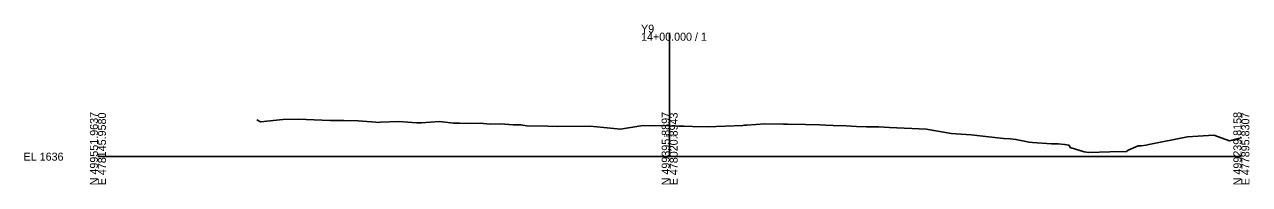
# Model space of a CAD drawing. Extents: x -26 to 403, y -99 to 4540.
# Drawn here: x -25.7 to 402.8, y 3990.3 to 4046.1 of the extents above; entities that cross this region are included whole.
import ezdxf

# ---------------------------------------------------------------- set-up
doc = ezdxf.new("R2010")
doc.units = 0
for name, color, linetype in [('Exist Cross Section Cell', 7, 'Continuous'), ('Exist XS Center Line Elevation Label', 7, 'Continuous'), ('Exist XS Ground Line', 7, 'Continuous')]:
    doc.layers.add(name, color=color, linetype=linetype)

msp = doc.modelspace()

# ---------------------------------------------------------------- linework, layer by layer
at = {"layer": 'Exist Cross Section Cell'}
for p, q in [((200, 4000), (200, 4043.26)), ((0, 4000), (200, 4000)), ((200, 4000), (400, 4000))]:
    msp.add_line(p, q, dxfattribs=at)
at = {"layer": 'Exist XS Ground Line'}
msp.add_lwpolyline([(55.54, 4012.85), (56.91, 4012.2), (64.71, 4013.01), (70.07, 4013.06), (81.2, 4012.6), (85.97, 4012.59), (90.99, 4012.54), (97.24, 4012.02), (98.1, 4011.97), (98.79, 4012), (105.22, 4012.3), (111.6, 4011.76), (112.33, 4011.81), (113.24, 4011.78), (119.45, 4012.26), (124.42, 4011.74), (126.56, 4011.71), (129.23, 4011.53), (133.68, 4011.68), (137.24, 4011.39), (140.79, 4011.5), (145.23, 4011.08), (147.91, 4011.06), (150.06, 4010.78), (157.38, 4010.69), (160.87, 4010.51), (172.13, 4010.63), (176.95, 4010.2), (182.79, 4009.58), (189.86, 4010.75), (190.87, 4010.93), (200, 4010.73), (203.22, 4010.66), (204.96, 4010.63), (207.94, 4010.52), (213.25, 4010.37), (225.54, 4010.89), (226.18, 4010.95), (226.96, 4011), (233.29, 4011.42), (239.77, 4011.31), (240.41, 4011.31), (241.2, 4011.32), (247.52, 4011.28), (252.59, 4011.08), (254.64, 4010.98), (257.19, 4010.88), (261.75, 4010.8), (265.41, 4010.57), (268.87, 4010.43), (273.19, 4010.41), (276.9, 4010.23), (289.8, 4009.6), (290.38, 4009.52), (291.09, 4009.42), (298.52, 4008.04), (305.47, 4007.58), (316.81, 4006.33), (319.15, 4006.17), (321.14, 4006.01), (325.8, 4005.01), (326.98, 4004.92), (333.57, 4004.53), (334.49, 4004.51), (335.88, 4004.48), (338.15, 4004.3), (339.74, 4003.98), (340.06, 4003.2), (344.98, 4001.74), (346.61, 4001.41), (354, 4001.64), (359.83, 4001.8), (360.4, 4002.32), (363.93, 4003.76), (364.92, 4003.75), (366.74, 4004.07), (367.59, 4004.22), (381.1, 4006.9), (390.42, 4007.53), (395.88, 4005.52), (398.97, 4006.34), (400, 4006.6)], dxfattribs=at)

# ---------------------------------------------------------------- texts
at = {"layer": 'Exist Cross Section Cell'}
for s, p in [('Y9', (190, 4043.26)), ('14+00.000 / 1', (190, 4040.46)), ('EL 1636', (-26, 3998.6))]:
    msp.add_text(s, height=2.8, dxfattribs=at).set_placement(p)
for s, p in [('N 499551.9637', (0, 3990)), ('N 499395.8897', (200, 3990)), ('N 499239.8158', (400, 3990)), ('E 478145.9580', (2.8, 3990)), ('E 478020.8943', (202.8, 3990)), ('E 477895.8307', (402.8, 3990))]:
    msp.add_text(s, height=2.8, rotation=90, dxfattribs=at).set_placement(p)
at = {"layer": 'Exist XS Center Line Elevation Label'}
msp.add_text('1646.73', height=0.9, dxfattribs=at).set_placement((197.93, 4006.83))

doc.saveas('drawing.dxf')
